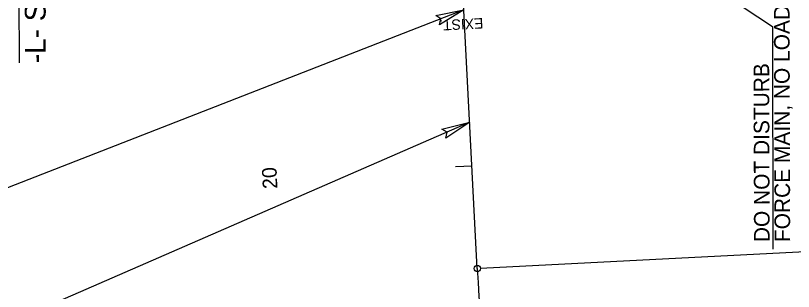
# Model space of a CAD drawing. Extents: x 1373164 to 1374172, y 550391 to 553180.
# Drawn here: x 1373512.6 to 1373885.8, y 551302.8 to 551435.1 of the extents above; entities that cross this region are included whole.
import ezdxf

# ---------------------------------------------------------------- set-up
doc = ezdxf.new("R2010")
doc.units = 0
for name, color, linetype in [('Exist Other Culture Gate Cogo Point CELL', 7, 'Continuous'), ('Exist Roads EOP Other Cogo Elevation', 7, 'Continuous'), ('Exist Structure Major Deck Tunnel Box Culvert Cogo Point CELL', 7, 'Continuous'), ('Exist Structure Minor Pipes RCP 18 Inch Cogo Comment', 7, 'Continuous'), ('Exist Structure Minor Pipes RCP 18 Inch Cogo Elevation', 7, 'Continuous'), ('Exist Structure Minor Pipes RCP 18 Inch Cogo Number', 7, 'Continuous'), ('Exist Utilities Sanitary Sewer Manhole Cogo Elevation', 7, 'Continuous')]:
    doc.layers.add(name, color=color, linetype=linetype)

msp = doc.modelspace()

# ---------------------------------------------------------------- linework, layer by layer
at = {"layer": 'Exist Roads EOP Other Cogo Elevation'}
msp.add_line((1373734.13, 551313.82), (1373707.02, 551838.37), dxfattribs=at)
msp.add_arc((1374474.15, 551352.06), 741, 182.95848, 199.57409, dxfattribs=at)
at = {"layer": 'Exist Structure Major Deck Tunnel Box Culvert Cogo Point CELL'}
for points in [[(1373714.3, 551435.1), (1373727.72, 551437.84), (1373715.95, 551430.67), (1373716.68, 551433.54)], [(1373714.3, 551435.1), (1373727.72, 551437.84), (1373715.95, 551430.67), (1373716.68, 551433.54)], [(1373717.2, 551380.66), (1373730.51, 551383.91), (1373719.02, 551376.3), (1373719.64, 551379.19)]]:
    msp.add_lwpolyline(points, close=True, dxfattribs=at)
at = {"layer": 'Exist Structure Minor Pipes RCP 18 Inch Cogo Comment'}
msp.add_line((1373731.6, 551362.94), (1373723.61, 551362.53), dxfattribs=at)
at = {"layer": 'Exist Structure Minor Pipes RCP 18 Inch Cogo Number'}
for p, q in [((1373730.51, 551383.91), (1373456.76, 551264.88)), ((1373735.63, 551313.89), (1374055.52, 551330.42))]:
    msp.add_line(p, q, dxfattribs=at)
msp.add_circle((1373734.13, 551313.82), 1.5, dxfattribs=at)
at = {"layer": 'Exist Utilities Sanitary Sewer Manhole Cogo Elevation'}
for p, q in [((1373514.04, 551577.79), (1373514.31, 551412.47)), ((1373759.5, 551506.97), (1373875.68, 551429.81)), ((1373875.68, 551429.81), (1373875.84, 551323.07))]:
    msp.add_line(p, q, dxfattribs=at)
msp.add_lwpolyline([(1373727.72, 551437.84), (1373383.63, 551303.77), (1373383.35, 551567.48)], dxfattribs=at)

# ---------------------------------------------------------------- texts
at = {"layer": 'Exist Other Culture Gate Cogo Point CELL'}
msp.add_text('EXIST.', height=5, rotation=182.9585, dxfattribs=at).set_placement((1373736.89, 551433.91))
at = {"layer": 'Exist Structure Minor Pipes RCP 18 Inch Cogo Elevation'}
msp.add_text('20', height=7, rotation=92.9585, dxfattribs=at).set_placement((1373638.29, 551352.15))
at = {"layer": 'Exist Structure Minor Pipes RCP 18 Inch Cogo Number'}
for s, height, rotation, p in [('-L- STA. 22+65.83', 10, 90.095, (1373527.11, 551412.26)), ('FORCE MAIN, NO LOADS', 7.5, 90.1567, (1373884.23, 551326.47)), ('DO NOT DISTURB', 7.5, 90.1567, (1373874.39, 551326.45))]:
    msp.add_text(s, height=height, rotation=rotation, dxfattribs=at).set_placement(p)

doc.saveas('drawing.dxf')
